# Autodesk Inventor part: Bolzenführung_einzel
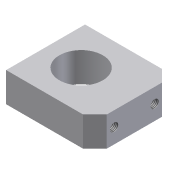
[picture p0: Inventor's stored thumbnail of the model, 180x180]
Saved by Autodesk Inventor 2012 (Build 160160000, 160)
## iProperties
Company: CAD-Verlag
Created: 2004-09
Part Number: Bolzenführung_einzel
Document SubType Name: Modeling
Designer: Greiling
Manufacturer: Standard
Standards Organization: Custom
Density: 1 g/cm^3
Checked By: Jürgen Kronas
Stock Number: 10-10014
Material: Standard
Author: Juergen Kronas
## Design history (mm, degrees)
sketch "Skizze1"
  geometry: L1 (0, 56)-(0, -56) reference; L2 (-54, 0)-(72, 0) reference; L3 (-54, 0)-(72, 0) reference; L4 (0, -56)-(0, 56) reference; L5 (-36, 40)-(42, 40); L6 (54, 28)-(54, -28); L7 (42, -40)-(-36, -40); L8 (-36, -40)-(-36, 40); L9 (54, 28)-(42, 40); L10 (42, -40)-(54, -28); C1 r 22 at (0, 0); 3 further points
  constraints: 12 end point, 4 point on line, 2 parallel, 1 centre point, 1 coincident, 1 horizontal, 1 perpendicular, 1 other
  dimensions: "d0" = 80 distance of L7.end L5.start; "d1" = 90 distance of L5.start point (54, 40); "d2" = 12 distance of L6.start point (54, 40); "d3" = 12 distance of L5.end point (54, 40) (= d2); "d4" = 12 distance of L7.start point (54, -40) (= d2); "d5" = 12 distance of L6.end point (54, -40) (= d4); "d6" = 54 distance between parallel lines of L1 L6; "d7" = 44 diameter of C1
extrude "Extrusion1" new body sketch "Skizze1" distance "d8" = 30; taper "d9" = 0 deg
sketch "Skizze2"
  geometry: L1 (0, 56)-(0, 0) reference; L2 (-36, 28)-(6, 28) reference; L3 (0, -28)-(0, 84) reference; 2 further points
  constraints: 1 symmetric about line
  dimensions: "d10" = 41 distance of point (-15, 7.5) point (-15, 48.5); "d11" = 15 distance from line of L1 point (-15, 48.5)
hole "Bohrung1" sketch "Skizze2" at (-15, 48.5), (-15, 7.5) diameter "d12" = 8.376; stored, may be unused: countersink angle "d16" = 90 deg, drill point angle "d18" = 118 deg; dims "d13" = 20, "d14" = 4.4, "d15" = 2, "d17" = 26
node "Volumenkörper1"
node "Volumenkörpern"
node "Oberflächenkörpern"
